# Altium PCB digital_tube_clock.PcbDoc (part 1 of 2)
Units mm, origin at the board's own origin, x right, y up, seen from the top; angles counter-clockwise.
Board outline 78.99 x 94.23 mm, 2 copper layers (Top Layer, Bottom Layer); 32 components, 49 nets, 189 pads, 6 vias.
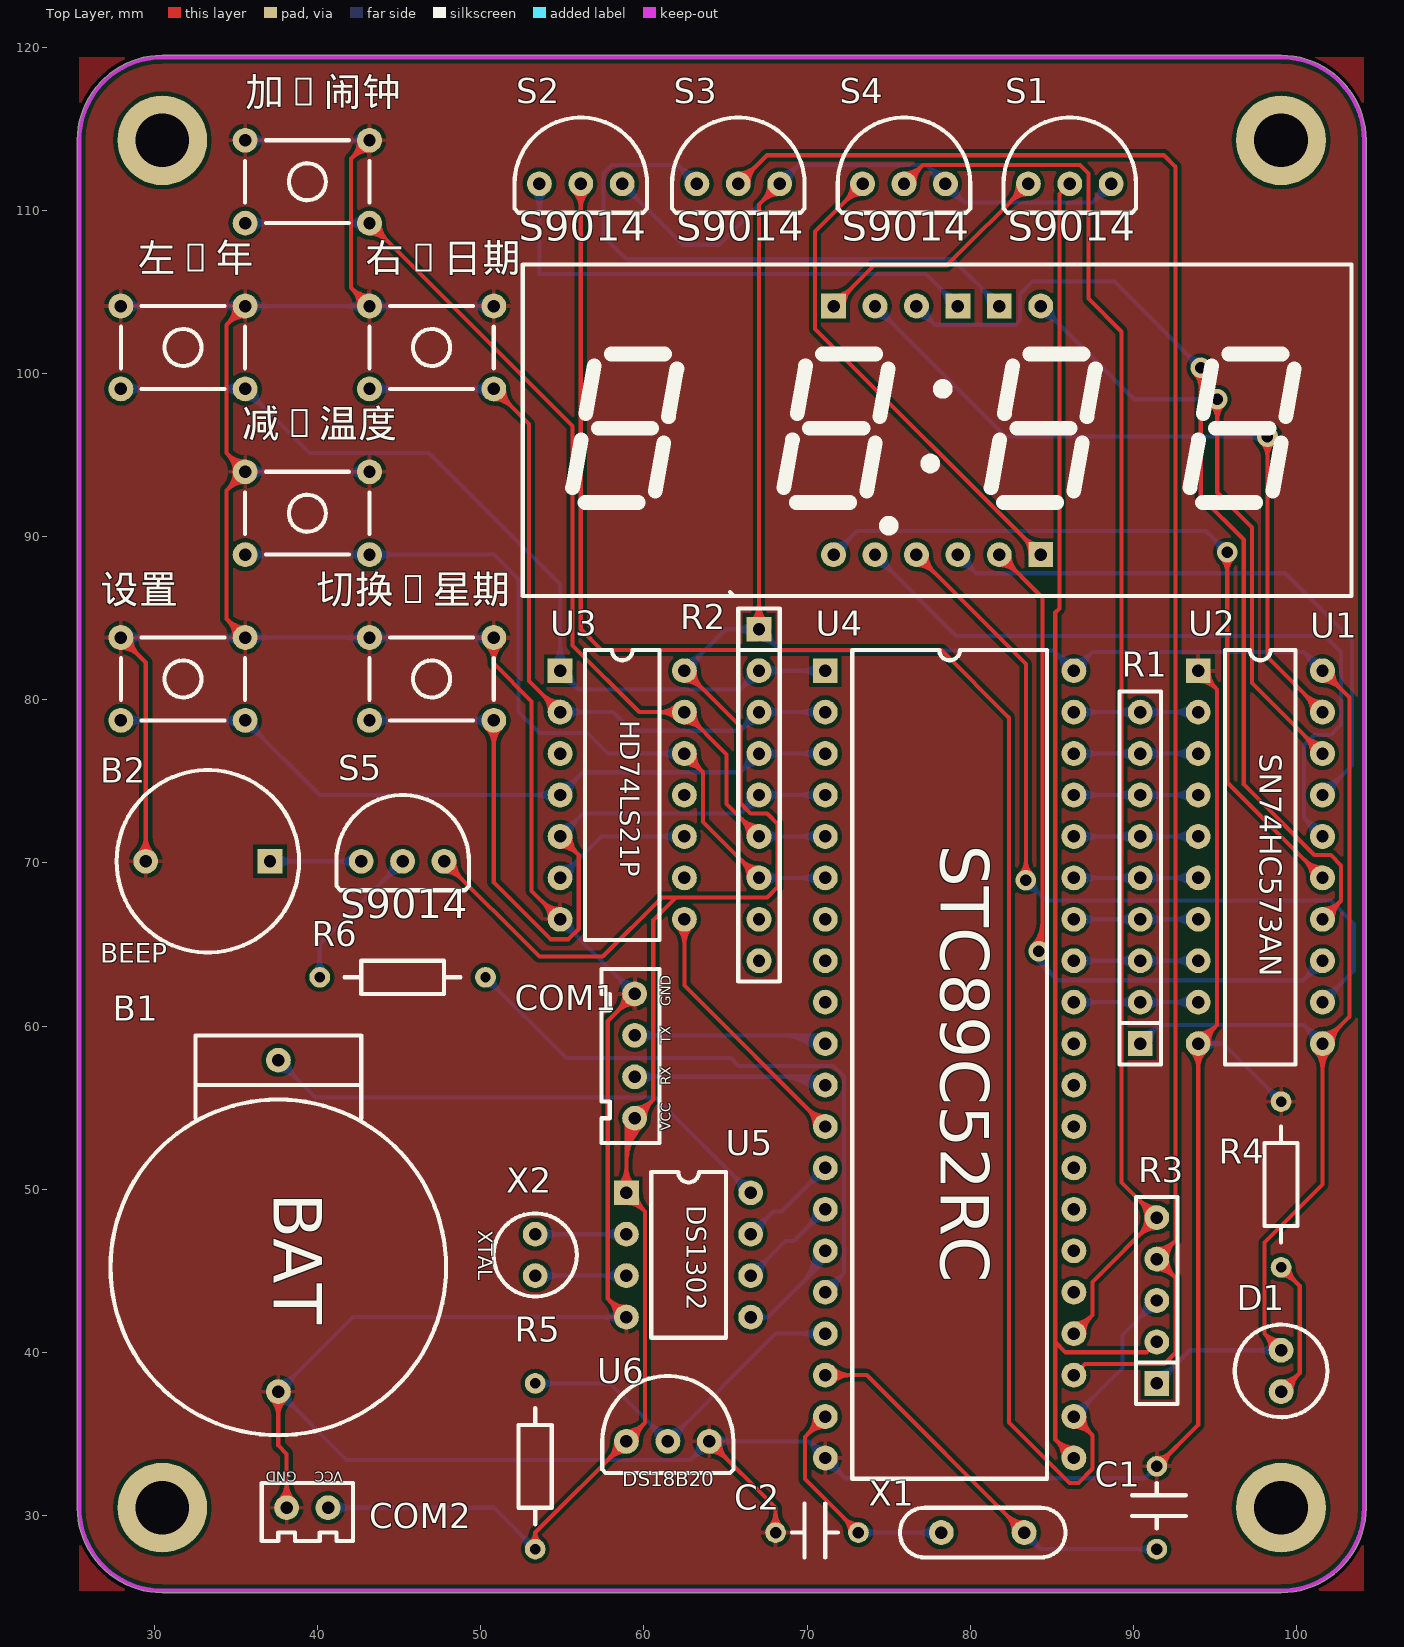
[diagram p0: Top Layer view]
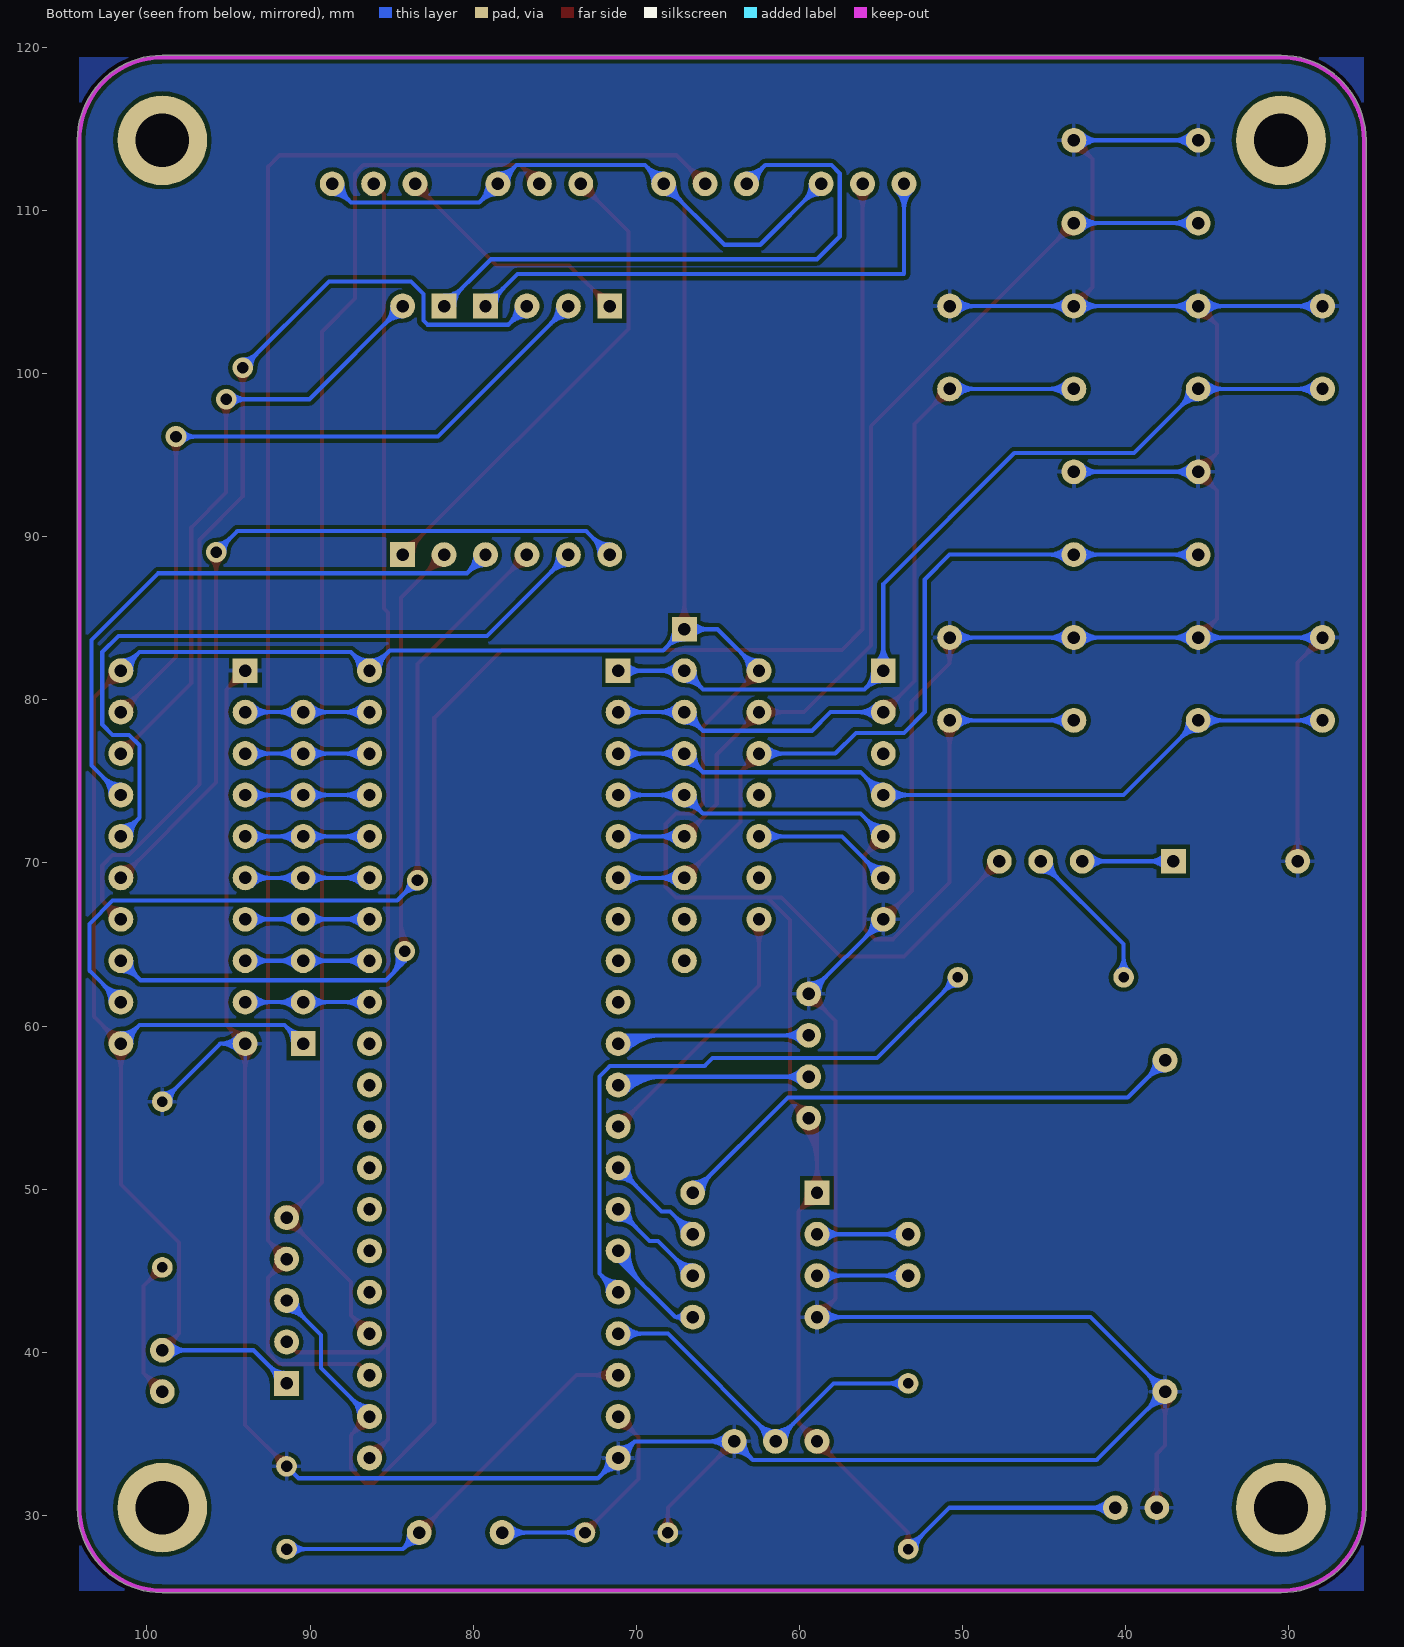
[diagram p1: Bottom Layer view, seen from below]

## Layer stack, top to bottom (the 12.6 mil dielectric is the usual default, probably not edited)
Top Layer: signal copper 0.0356
Dielectric: dielectric 0.32, FR-4, Dk 4.8
Bottom Layer: signal copper 0.0356

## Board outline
25.273,30.479 cw(c30.48,30.48) 25.273,30.48 25.273,114.3 cw(c30.48,114.3) 30.48,119.507 99.06,119.507 cw(c99.06,114.3) 104.267,114.301 cw(c104.14,114.3) 104.267,114.3 104.267,30.48 cw(c99.06,30.48) 99.061,25.273 cw(c99.06,25.4) 99.06,25.273 30.48,25.273 cw(c30.48,30.48)

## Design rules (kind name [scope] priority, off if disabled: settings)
Clearance [All] p1: gap=0.254
ComponentClearance [All] p1: gap=0.254 collisioncheckmode=3 verticalgap=0.254
PolygonConnect [All] p1: connectstyle=Relief reliefconductorwidth=0.254 reliefentries=4 polygonreliefangle="90 Angle"
RoutingVias [All] p1: holewidth=0.711 width=1.27 viastyle="Through Hole" minholewidth=0.711 minwidth=1.27 maxholewidth=0.711 maxwidth=1.27
SolderMaskExpansion [All] p1: expansion=0.102
TestPointUsage [All] p1: valid=0 allowmultiple=FALSE
Testpoint [All] p1: side=15 testpointundercomponent=TRUE minsize=1.016 maxsize=2.54 preferedsize=1.524 minholesize=0 maxholesize=1.016 preferedholesize=0.813 testpointgrid=0.025 style=1023 order=0123456789
Width [All] p1: maxlimit=0.254 minlimit=0.254 preferedwidth=0.254
18 further rules are at their usual default settings.

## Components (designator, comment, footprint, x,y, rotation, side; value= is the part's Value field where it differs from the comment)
B1 "BATTERY" BAT 35.052,57.912 r0 top
B2 "BEEP" BEEP 37.084,70.104 r180 top
C1 "CAP" CAP 91.44,35.56 r270 top
C2 "CAP" CAP 65.532,28.956 r0 top
COM1 "COM" COM4 59.436,54.356 r90 top
COM2 "COM" COM2 43.18,30.48 r180 top
D1 "LED" LED 99.06,40.132 r270 top
R1 "RES8" RES8 90.424,58.928 r180 top
R2 "RES8" RES8 67.056,84.328 r0 top
R3 "RES4" RES4 91.44,38.1 r180 top
R4 "RES" RES 99.06,45.212 r90 top
R5 "RES" RES 53.34,38.1 r270 top
R6 "RES" RES 50.292,62.992 r180 top
S1 "S9014" S9014 83.566,111.633 r0 top
S2 "S9014" S9014 53.594,111.633 r0 top
S3 "S9014" S9014 63.246,111.633 r0 top
S4 "S9014" S9014 73.406,111.633 r0 top
S5 "S9014" S9014 42.672,70.104 r0 top
U1 "DIGITAL_TUBE" DIGITAL 51.308,106.68 r0 top
U2 "SN74HC573AN" SN74HC573AN 93.98,81.788 r0 top
U3 "HD74LS21P" HD74LS21P 54.864,81.788 r0 top
U4 "STC89C52RC" STC89C52RC 71.12,81.788 r0 top
U5 "DS1302" DS1302 58.928,49.784 r0 top
U6 "DS18B20" DS18B20 58.928,34.544 r0 top
X1 "XTAL" XTAL 78.232,28.956 r0 top
X2 "36" XTAL36 53.34,47.244 r270 top
减/温度 "BUTTON" BUTTON 35.56,93.98 r0 top (schematic designator K6)
切换/星期 "BUTTON" BUTTON 43.18,83.82 r0 top (schematic designator K4)
加/闹钟 "BUTTON" BUTTON 35.56,114.3 r0 top (schematic designator K5)
右/日期 "BUTTON" BUTTON 43.18,104.14 r0 top (schematic designator K2)
左/年 "BUTTON" BUTTON 27.94,104.14 r0 top (schematic designator K1)
设置 "BUTTON" BUTTON 27.94,83.82 r0 top (schematic designator K3)

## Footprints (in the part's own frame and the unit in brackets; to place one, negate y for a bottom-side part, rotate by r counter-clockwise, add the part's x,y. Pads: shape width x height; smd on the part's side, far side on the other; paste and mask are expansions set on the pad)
BAT [mil]
  round 60 hole 30: GND(100,-800) VCC(100,0)
  silkscreen extent -305,-905 505,60
BEEP [mil]
  rect 60x60 hole 30: 1(0,0)
  round 60 hole 30: 2(300,0)
  silkscreen extent -70,-220 370,220
BUTTON [mil]
  round 60 hole 30: 1(0,0) 1(300,0) 2(0,-200) 2(300,-200)
  silkscreen extent 0,-200 300,0
CAP [mil]
  round 50 hole 28: 1(100,0) 2(300,0)
  silkscreen extent 140,-60 250,70
COM2 [mil]
  round 60 hole 30: GND(200,0) VCC(100,0)
  silkscreen extent 40,-60 260,80
COM4 [mil]
  round 60 hole 30: GND(300,0) RX(100,0) TX(200,0) VCC(0,0)
  silkscreen extent -60,-60 360,80
DIGITAL [mil] "LED, 7-Segment Display, 10 mm, Three Digit; 15 Leads (4 Absent); Row Space 10.16 mm; Pitch 2.54 mm"
  rect 60x60 hole 30: 1(800,-100) 2(1100,-100) 3(1200,-100) 4(1300,-700)
  round 60 hole 30: a(900,-100) b(1300,-100) c(1100,-700) d(900,-700) e(800,-700) f(1000,-100) g(1200,-700) h(1000,-700)
  silkscreen extent 50,-800 2050,0
DS18B20 [mil]
  round 60 hole 30: DQ(100,0) GND(200,0) VDD(0,0)
  silkscreen extent -58,-76 258,158
DS1302 [mil]
  rect 60x60 hole 30: 1(0,0)
  round 60 hole 30: 2(0,-100) 3(0,-200) 4(0,-300) 5(300,-300) 6(300,-200) 7(300,-100) 8(300,0)
  silkscreen extent 60,-350 240,50
HD74LS21P [mil]
  rect 60x60 hole 30: 1(0,0)
  round 60 hole 30: 2(0,-100) 3(0,-200) 4(0,-300) 5(0,-400) 6(0,-500) 7(0,-600) 8(300,-600) 9(300,-500) 10(300,-400) 11(300,-300) 12(300,-200) 13(300,-100) 14(300,0)
  silkscreen extent 60,-650 240,50
LED [mil]
  round 60 hole 30: 1(0,0) 2(100,0)
  silkscreen extent -62,-112 162,112
RES [mm]
  round 1.27 hole 0.635: 1(0,0) 2(10.16,0)
  silkscreen extent 1.52,-1.02 8.64,1.02
RES4 [mil]
  rect 60x60 hole 30: 1(0,0)
  round 60 hole 30: 2(0,-100) 3(0,-200) 4(0,-300) 5(0,-400)
  silkscreen extent -50,-450 50,50
RES8 [mil]
  rect 60x60 hole 30: 1(0,0)
  round 60 hole 30: 2(0,-100) 3(0,-200) 4(0,-300) 5(0,-400) 6(0,-500) 7(0,-600) 8(0,-700) 9(0,-800)
  silkscreen extent -50,-850 50,50
S9014 [mil]
  round 60 hole 30: b(100,0) c(200,0) e(0,0)
  silkscreen extent -60,-70 260,160
SN74HC573AN [mil]
  rect 60x60 hole 30: 1(0,0)
  round 60 hole 30: 2(0,-100) 3(0,-200) 4(0,-300) 5(0,-400) 6(0,-500) 7(0,-600) 8(0,-700) 9(0,-800) 10(0,-900) 11(300,-900) 12(300,-800) 13(300,-700) 14(300,-600) 15(300,-500) 16(300,-400) 17(300,-300) 18(300,-200) 19(300,-100) 20(300,0)
  silkscreen extent 65,-950 235,50
STC89C52RC [mil]
  rect 60x60 / inner rect 60x6 / far side rect 60x60 hole 30: 1(0,0)
  round 60 / inner oval 60x6 / far side round 60 hole 30: 2(0,-100) 3(0,-200) 4(0,-300) 5(0,-400) 6(0,-500) 7(0,-600) 8(0,-700) 9(0,-800) 10(0,-900) 11(0,-1000) 12(0,-1100) 13(0,-1200) 14(0,-1300) 15(0,-1400) 16(0,-1500) 17(0,-1600) 18(0,-1700) 19(0,-1800) 20(0,-1900) 21(600,-1900) 22(600,-1800) 23(600,-1700) 24(600,-1600) 25(600,-1500) 26(600,-1400) 27(600,-1300) 28(600,-1200) 29(600,-1100) 30(600,-1000) 31(600,-900) 32(600,-800) 33(600,-700) 34(600,-600) 35(600,-500) 36(600,-400) 37(600,-300) 38(600,-200) 39(600,-100) 40(600,0)
  silkscreen extent 65,-1950 535,50
XTAL [mil]
  round 60 hole 30: 1(0,0) 2(200,0)
  silkscreen extent -100,-60 300,60
XTAL36 [mil]
  round 60 hole 30: 1(100,0) 2(0,0)
  silkscreen extent -50,-100 150,100

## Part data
C1 C2: "Capacitance"
COM1: library part COM4, "Download interface"
COM2: library part COM2, "Power interface"
D1: "The power led"
R1 R2: "Resistance * 8"
R3: "Resistance * 4"
R4 R5 R6: "Resistance"
U1: "Dispaly panel"
U4: "8-Bit Microcontroller with 8K ISP Flash ROM"
U5: "Trickle Charge Timekeeping Chip"
U6: library part D18B20, "Programmable Resolution  1-Wire Digital Thermometer"
X1: "Generate system clock"
X2: library part XTAL36

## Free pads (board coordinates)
  round 5.5 hole 3.3: 0(30.48,114.3) 1(99.06,114.3) 2(30.48,30.48) 3(99.06,30.48)

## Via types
v1: diameter 1.27, hole 0.711, Top Layer to Bottom Layer, 6 vias

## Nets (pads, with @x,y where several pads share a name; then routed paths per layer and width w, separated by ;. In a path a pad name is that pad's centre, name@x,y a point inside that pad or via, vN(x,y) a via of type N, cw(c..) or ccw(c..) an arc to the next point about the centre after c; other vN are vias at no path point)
BEEP: R6.1 U4.16 | length 44
  Bottom Layer w0.254: R6.1@50.292,62.484 cw(c50.292,61.258) 51.159,62.125 cw(c52.026,62.992) R6.1@50.8,62.992 ; R6.1@50.292,62.992 55.245,58.039 65.329,58.039 65.811,57.556 71.628,57.556 72.263,56.921 72.263,44.831 U4.16@71.12,43.688 ; U4.16@71.12,44.069 ccw(c71.12,44.989) 71.77,44.338 ccw(c72.421,43.688) U4.16@71.501,43.688 ; U4.16@71.12,44.323 ccw(c71.12,45.856) 72.204,44.772 ccw(c73.288,43.688) U4.16@71.755,43.688
DATA: U4.14 U5.6 | length 14
  Bottom Layer w0.254: U5.6@66.548,44.704 68.679,46.835 69.187,46.835 U4.14@71.12,48.768 ; U5.6@66.548,45.085 ccw(c66.548,46.005) 67.198,45.354 ccw(c67.849,44.704) U5.6@66.929,44.704 ; U5.6@66.548,45.339 ccw(c66.548,46.872) 67.632,45.788 ccw(c68.716,44.704) U5.6@67.183,44.704 ; U4.14@70.485,48.768 cw(c68.952,48.768) 70.036,47.684 cw(c71.12,46.6) U4.14@71.12,48.133 ; U4.14@70.739,48.768 cw(c69.819,48.768) 70.47,48.118 cw(c71.12,47.467) U4.14@71.12,48.387
DIG1: R3.2 S1.b U4.21 | length 89.5
  Top Layer w0.254: U4.21@85.725,33.528 ccw(c84.192,33.528) 85.276,34.612 ccw(c86.36,35.696) U4.21@86.36,34.163 ; U4.21@85.979,33.528 ccw(c85.059,33.528) 85.71,34.178 ccw(c86.36,34.829) U4.21@86.36,33.909 ; S1.b@86.106,111.633 85.471,110.998 85.471,85.598 85.217,85.344 85.217,40.64 ; U4.21@86.36,33.528 85.217,34.671 85.217,40.64 ; R3.2@91.44,40.64 90.805,40.005 85.852,40.005 85.217,40.64
DIG2: R3.3 S2.b U4.22 | length 134.3
  Top Layer w0.254: S2.b@55.685,111.184 cw(c54.601,110.1) 56.134,110.1 cw(c57.667,110.1) S2.b@56.583,111.184 ; S2.b@55.865,111.364 cw(c55.214,110.713) 56.134,110.713 cw(c57.054,110.713) S2.b@56.403,111.364 ; S2.b@56.134,111.633 56.134,84.328 57.404,83.058 78.232,83.058 82.39,78.9 82.39,35.694 86.081,32.004 86.639,32.004 87.503,32.868 87.503,34.925 U4.22@86.36,36.068 ; U4.22@86.36,35.433 cw(c86.36,33.9) 87.444,34.984 cw(c88.528,36.068) U4.22@86.995,36.068 ; U4.22@86.36,35.687 cw(c86.36,34.767) 87.01,35.418 cw(c87.661,36.068) U4.22@86.741,36.068
  Bottom Layer w0.254: U4.22@86.36,36.068 89.332,39.04 89.332,41.072 R3.3@91.44,43.18 ; U4.22@86.36,36.449 ccw(c86.36,37.369) 87.01,36.718 ccw(c87.661,36.068) U4.22@86.741,36.068 ; U4.22@86.36,36.703 ccw(c86.36,38.236) 87.444,37.152 ccw(c88.528,36.068) U4.22@86.995,36.068 ; R3.3@90.805,43.18 cw(c89.272,43.18) 90.356,42.096 cw(c91.44,41.012) R3.3@91.44,42.545 ; R3.3@91.059,43.18 cw(c90.139,43.18) 90.79,42.53 cw(c91.44,41.879) R3.3@91.44,42.799
DIG3: R3.4 S3.b U4.23 | length 119.8
  Top Layer w0.254: S3.b@65.786,111.633 67.539,113.386 91.872,113.386 92.583,112.674 92.583,46.863 R3.4@91.44,45.72 92.583,44.577 92.583,39.98 91.897,39.294 87.046,39.294 U4.23@86.36,38.608 ; S3.b@65.786,112.014 ccw(c65.786,112.934) 66.436,112.283 ccw(c67.087,111.633) S3.b@66.167,111.633 ; S3.b@65.786,112.268 ccw(c65.786,113.801) 66.87,112.717 ccw(c67.954,111.633) S3.b@66.421,111.633 ; R3.4@91.44,45.085 cw(c91.44,43.552) 92.524,44.636 cw(c93.608,45.72) 92.075,45.72 cw(c93.608,45.72) 92.524,46.804 cw(c91.44,47.888) R3.4@91.44,46.355 ; R3.4@91.44,45.339 cw(c91.44,44.419) 92.09,45.07 cw(c92.741,45.72) 91.821,45.72 cw(c92.741,45.72) 92.09,46.37 cw(c91.44,47.021) R3.4@91.44,46.101
DIG4: R3.5 S4.b U4.24 | length 102.4
  Top Layer w0.254: S4.b@75.946,111.633 77.089,112.776 86.741,112.776 87.249,112.268 87.249,104.597 89.281,102.565 89.281,50.419 R3.5@91.44,48.26 87.503,44.323 87.503,42.291 U4.24@86.36,41.148 ; S4.b@75.946,112.014 ccw(c75.946,112.934) 76.596,112.283 ccw(c77.247,111.633) S4.b@76.327,111.633 ; S4.b@75.946,112.268 ccw(c75.946,113.801) 77.03,112.717 ccw(c78.114,111.633) S4.b@76.581,111.633 ; U4.24@86.36,41.529 ccw(c86.36,42.449) 87.01,41.798 ccw(c87.661,41.148) U4.24@86.741,41.148 ; U4.24@86.36,41.783 ccw(c86.36,43.316) 87.444,42.232 ccw(c88.528,41.148) U4.24@86.995,41.148 ; R3.5@91.44,47.625 ccw(c91.44,46.092) 90.356,47.176 ccw(c89.272,48.26) 90.805,48.26 ccw(c89.272,48.26) 90.356,49.344 ccw(c91.44,50.428) R3.5@91.44,48.895 ; R3.5@91.44,47.879 ccw(c91.44,46.959) 90.79,47.61 ccw(c90.139,48.26) 91.059,48.26 ccw(c90.139,48.26) 90.79,48.91 ccw(c91.44,49.561) R3.5@91.44,48.641
DQ: R5.1 U4.17 U6.DQ | length 35.5
  Bottom Layer w0.254: R5.1@53.34,38.1 57.912,38.1 U6.DQ@61.468,34.544 68.072,41.148 U4.17@71.12,41.148 ; R5.1@53.699,37.741 cw(c54.566,36.874) 54.566,38.1 cw(c54.566,39.326) R5.1@53.699,38.459 ; U6.DQ@60.833,34.544 ccw(c59.3,34.544) 60.384,35.628 ccw(c61.468,36.712) 61.468,35.179 ccw(c61.468,36.712) 62.552,35.628 ccw(c63.636,34.544) U6.DQ@62.103,34.544 ; U6.DQ@61.087,34.544 ccw(c60.167,34.544) 60.818,35.194 ccw(c61.468,35.845) 61.468,34.925 ccw(c61.468,35.845) 62.118,35.194 ccw(c62.769,34.544) U6.DQ@61.849,34.544 ; U4.17@70.671,40.699 ccw(c69.587,39.615) 69.587,41.148 ccw(c69.587,42.681) U4.17@70.671,41.597 ; U4.17@70.851,40.879 ccw(c70.2,40.228) 70.2,41.148 ccw(c70.2,42.068) U4.17@70.851,41.417
GND: B1.GND B2.2 C1.1 C2.1 COM1.GND COM2.GND R4.2 U2.1 U2.10 U3.7 U4.20 U5.4 U6.GND 减/温度.1 切换/星期.1 加/闹钟.1 右/日期.1 左/年.1 设置.1 | length 482.4
  Top Layer w0.254: 设置.1@27.94,83.185 cw(c27.94,81.652) 29.024,82.736 cw(c30.108,83.82) 设置.1@28.575,83.82 ; 设置.1@27.94,83.439 cw(c27.94,82.519) 28.59,83.17 cw(c29.241,83.82) 设置.1@28.321,83.82 ; 设置.1@27.94,83.82 29.464,82.296 B2.2@29.464,70.104 ; B2.2@29.015,70.553 ccw(c27.931,71.637) 29.464,71.637 ccw(c30.997,71.637) B2.2@29.913,70.553 ; B2.2@29.195,70.373 ccw(c28.544,71.024) 29.464,71.024 ccw(c30.384,71.024) B2.2@29.733,70.373 ; 设置.1@34.925,83.82 ccw(c33.392,83.82) 34.476,84.904 ccw(c35.56,85.988) 设置.1@35.56,84.455 ; 左/年.1@34.925,104.14 cw(c33.392,104.14) 34.476,103.056 cw(c35.56,101.972) 左/年.1@35.56,103.505 ; 设置.1@35.179,83.82 ccw(c34.259,83.82) 34.91,84.47 ccw(c35.56,85.121) 设置.1@35.56,84.201 ; 左/年.1@35.179,104.14 cw(c34.259,104.14) 34.91,103.49 cw(c35.56,102.839) 左/年.1@35.56,103.759 ; 设置.1@35.56,83.82 34.417,84.963 34.417,92.837 减/温度.1@35.56,93.98 34.417,95.123 34.417,102.997 左/年.1@35.56,104.14 ; 减/温度.1@35.56,93.345 ccw(c35.56,91.812) 34.476,92.896 ccw(c33.392,93.98) 34.925,93.98 ccw(c33.392,93.98) 34.476,95.064 ccw(c35.56,96.148) 减/温度.1@35.56,94.615 ; 减/温度.1@35.56,93.599 ccw(c35.56,92.679) 34.91,93.33 ccw(c34.259,93.98) 35.179,93.98 ccw(c34.259,93.98) 34.91,94.63 ccw(c35.56,95.281) 减/温度.1@35.56,94.361 ; B1.GND@37.143,37.143 cw(c36.059,36.059) 37.592,36.059 cw(c39.125,36.059) B1.GND@38.041,37.143 ; B1.GND@37.323,37.323 cw(c36.672,36.672) 37.592,36.672 cw(c38.512,36.672) B1.GND@37.861,37.323 ; B1.GND@37.592,37.592 37.592,34.29 38.1,33.782 COM2.GND@38.1,30.48 ; COM2.GND@37.651,30.929 ccw(c36.567,32.013) 38.1,32.013 ccw(c39.633,32.013) COM2.GND@38.549,30.929 ; COM2.GND@37.831,30.749 ccw(c37.18,31.4) 38.1,31.4 ccw(c39.02,31.4) COM2.GND@38.369,30.749 ; 右/日期.1@42.545,104.14 ccw(c41.012,104.14) 42.096,105.224 ccw(c43.18,106.308) 右/日期.1@43.18,104.775 ; 加/闹钟.1@42.545,114.3 cw(c41.012,114.3) 42.096,113.216 cw(c43.18,112.132) 加/闹钟.1@43.18,113.665 ; 右/日期.1@42.799,104.14 ccw(c41.879,104.14) 42.53,104.79 ccw(c43.18,105.441) 右/日期.1@43.18,104.521 ; 加/闹钟.1@42.799,114.3 cw(c41.879,114.3) 42.53,113.65 cw(c43.18,112.999) 加/闹钟.1@43.18,113.919 ; 右/日期.1@43.18,104.14 42.037,105.283 42.037,113.157 加/闹钟.1@43.18,114.3 ; 切换/星期.1@50.351,83.371 cw(c49.267,82.287) 50.8,82.287 cw(c52.333,82.287) 切换/星期.1@51.249,83.371 ; 切换/星期.1@50.531,83.551 cw(c49.88,82.9) 50.8,82.9 cw(c51.72,82.9) 切换/星期.1@51.069,83.551 ; 切换/星期.1@50.8,83.82 50.8,82.22 53.119,79.901 53.119,68.293 U3.7@54.864,66.548 ; U3.7@54.229,66.548 ccw(c52.696,66.548) 53.78,67.632 ccw(c54.864,68.716) U3.7@54.864,67.183 ; U3.7@54.483,66.548 ccw(c53.563,66.548) 54.214,67.198 ccw(c54.864,67.849) U3.7@54.864,66.929 ; U5.4@58.293,42.164 ccw(c56.76,42.164) 57.844,43.248 ccw(c58.928,44.332) U5.4@58.928,42.799 ; U5.4@58.547,42.164 ccw(c57.627,42.164) 58.278,42.814 ccw(c58.928,43.465) U5.4@58.928,42.545 ; COM1.GND@58.801,61.976 cw(c57.268,61.976) 58.352,60.892 cw(c59.436,59.808) COM1.GND@59.436,61.341 ; U5.4@58.928,42.164 57.785,43.307 57.785,60.325 COM1.GND@59.436,61.976 ; COM1.GND@59.055,61.976 cw(c58.135,61.976) 58.786,61.326 cw(c59.436,60.675) COM1.GND@59.436,61.595 ; U6.GND@64.008,33.909 cw(c64.008,32.376) 65.092,33.46 cw(c66.176,34.544) U6.GND@64.643,34.544 ; U6.GND@64.008,34.163 cw(c64.008,33.243) 64.658,33.894 cw(c65.309,34.544) U6.GND@64.389,34.544 ; U6.GND@64.008,34.544 68.072,30.48 C2.1@68.072,28.956 ; C2.1@67.713,29.315 ccw(c66.846,30.182) 68.072,30.182 ccw(c69.298,30.182) C2.1@68.431,29.315 ; C1.1@91.44,33.02 93.98,35.56 U2.10@93.98,58.928 95.123,60.071 95.123,80.645 U2.1@93.98,81.788 ; C1.1@91.44,33.528 ccw(c91.44,34.754) 92.307,33.887 ccw(c93.174,33.02) C1.1@91.948,33.02 ; U2.10@93.531,58.479 cw(c92.447,57.395) 93.98,57.395 cw(c95.513,57.395) U2.10@94.429,58.479 ; U2.10@93.711,58.659 cw(c93.06,58.008) 93.98,58.008 cw(c94.9,58.008) U2.10@94.249,58.659 ; U2.10@93.98,59.309 ccw(c93.98,60.229) 94.63,59.578 ccw(c95.281,58.928) U2.10@94.361,58.928 ; U2.10@93.98,59.563 ccw(c93.98,61.096) 95.064,60.012 ccw(c96.148,58.928) U2.10@94.615,58.928 ; U2.1@93.98,81.153 cw(c93.98,79.62) 95.064,80.704 cw(c96.148,81.788) U2.1@94.615,81.788 ; U2.1@93.98,81.407 cw(c93.98,80.487) 94.63,81.138 cw(c95.281,81.788) U2.1@94.361,81.788
  Bottom Layer w0.254: 设置.1@27.94,83.82 设置.1@35.56,83.82 切换/星期.1@43.18,83.82 切换/星期.1@50.8,83.82 ; 左/年.1@27.94,104.14 左/年.1@35.56,104.14 右/日期.1@43.18,104.14 右/日期.1@50.8,104.14 ; 设置.1@28.209,83.551 cw(c28.86,82.9) 28.86,83.82 cw(c28.86,84.74) 设置.1@28.209,84.089 ; 左/年.1@28.209,103.871 cw(c28.86,103.22) 28.86,104.14 cw(c28.86,105.06) 左/年.1@28.209,104.409 ; 设置.1@28.389,83.371 cw(c29.473,82.287) 29.473,83.82 cw(c29.473,85.353) 设置.1@28.389,84.269 ; 左/年.1@28.389,103.691 cw(c29.473,102.607) 29.473,104.14 cw(c29.473,105.673) 左/年.1@28.389,104.589 ; 设置.1@35.111,83.371 ccw(c34.027,82.287) 34.027,83.82 ccw(c34.027,85.353) 设置.1@35.111,84.269 ; 左/年.1@35.111,103.691 ccw(c34.027,102.607) 34.027,104.14 ccw(c34.027,105.673) 左/年.1@35.111,104.589 ; 设置.1@35.291,83.551 ccw(c34.64,82.9) 34.64,83.82 ccw(c34.64,84.74) 设置.1@35.291,84.089 ; 左/年.1@35.291,103.871 ccw(c34.64,103.22) 34.64,104.14 ccw(c34.64,105.06) 左/年.1@35.291,104.409 ; 减/温度.1@35.56,93.98 减/温度.1@43.18,93.98 ; 加/闹钟.1@35.56,114.3 加/闹钟.1@43.18,114.3 ; 设置.1@35.829,83.551 cw(c36.48,82.9) 36.48,83.82 cw(c36.48,84.74) 设置.1@35.829,84.089 ; 减/温度.1@35.829,93.711 cw(c36.48,93.06) 36.48,93.98 cw(c36.48,94.9) 减/温度.1@35.829,94.249 ; 左/年.1@35.829,103.871 cw(c36.48,103.22) 36.48,104.14 cw(c36.48,105.06) 左/年.1@35.829,104.409 ; 加/闹钟.1@35.829,114.031 cw(c36.48,113.38) 36.48,114.3 cw(c36.48,115.22) 加/闹钟.1@35.829,114.569 ; 设置.1@36.009,83.371 cw(c37.093,82.287) 37.093,83.82 cw(c37.093,85.353) 设置.1@36.009,84.269 ; 减/温度.1@36.009,93.531 cw(c37.093,92.447) 37.093,93.98 cw(c37.093,95.513) 减/温度.1@36.009,94.429 ; 左/年.1@36.009,103.691 cw(c37.093,102.607) 37.093,104.14 cw(c37.093,105.673) 左/年.1@36.009,104.589 ; 加/闹钟.1@36.009,113.851 cw(c37.093,112.767) 37.093,114.3 cw(c37.093,115.833) 加/闹钟.1@36.009,114.749 ; B1.GND@37.592,36.957 cw(c37.592,35.424) 38.676,36.508 cw(c39.76,37.592) 38.227,37.592 cw(c39.76,37.592) 38.676,38.676 cw(c37.592,39.76) B1.GND@37.592,38.227 ; B1.GND@37.592,37.211 cw(c37.592,36.291) 38.242,36.942 cw(c38.893,37.592) 37.973,37.592 cw(c38.893,37.592) 38.242,38.242 cw(c37.592,38.893) B1.GND@37.592,37.973 ; 切换/星期.1@42.731,83.371 ccw(c41.647,82.287) 41.647,83.82 ccw(c41.647,85.353) 切换/星期.1@42.731,84.269 ; 减/温度.1@42.731,93.531 ccw(c41.647,92.447) 41.647,93.98 ccw(c41.647,95.513) 减/温度.1@42.731,94.429 ; 右/日期.1@42.731,103.691 ccw(c41.647,102.607) 41.647,104.14 ccw(c41.647,105.673) 右/日期.1@42.731,104.589 ; 加/闹钟.1@42.731,113.851 ccw(c41.647,112.767) 41.647,114.3 ccw(c41.647,115.833) 加/闹钟.1@42.731,114.749 ; 切换/星期.1@42.911,83.551 ccw(c42.26,82.9) 42.26,83.82 ccw(c42.26,84.74) 切换/星期.1@42.911,84.089 ; 减/温度.1@42.911,93.711 ccw(c42.26,93.06) 42.26,93.98 ccw(c42.26,94.9) 减/温度.1@42.911,94.249 ; 右/日期.1@42.911,103.871 ccw(c42.26,103.22) 42.26,104.14 ccw(c42.26,105.06) 右/日期.1@42.911,104.409 ; 加/闹钟.1@42.911,114.031 ccw(c42.26,113.38) 42.26,114.3 ccw(c42.26,115.22) 加/闹钟.1@42.911,114.569 ; 切换/星期.1@43.449,83.551 cw(c44.1,82.9) 44.1,83.82 cw(c44.1,84.74) 切换/星期.1@43.449,84.089 ; 右/日期.1@43.449,103.871 cw(c44.1,103.22) 44.1,104.14 cw(c44.1,105.06) 右/日期.1@43.449,104.409 ; 切换/星期.1@43.629,83.371 cw(c44.713,82.287) 44.713,83.82 cw(c44.713,85.353) 切换/星期.1@43.629,84.269 ; 右/日期.1@43.629,103.691 cw(c44.713,102.607) 44.713,104.14 cw(c44.713,105.673) 右/日期.1@43.629,104.589 ; 切换/星期.1@50.351,83.371 ccw(c49.267,82.287) 49.267,83.82 ccw(c49.267,85.353) 切换/星期.1@50.351,84.269 ; 右/日期.1@50.351,103.691 ccw(c49.267,102.607) 49.267,104.14 ccw(c49.267,105.673) 右/日期.1@50.351,104.589 ; 切换/星期.1@50.531,83.551 ccw(c49.88,82.9) 49.88,83.82 ccw(c49.88,84.74) 切换/星期.1@50.531,84.089 ; 右/日期.1@50.531,103.871 ccw(c49.88,103.22) 49.88,104.14 ccw(c49.88,105.06) 右/日期.1@50.531,104.409 ; U3.7@54.864,65.913 cw(c54.864,64.38) 55.948,65.464 cw(c57.032,66.548) U3.7@55.499,66.548 ; U3.7@54.864,66.167 cw(c54.864,65.247) 55.514,65.898 cw(c56.165,66.548) U3.7@55.245,66.548 ; U3.7@54.864,66.548 COM1.GND@59.436,61.976 ; U5.4@58.479,41.715 ccw(c57.395,40.631) 57.395,42.164 ccw(c57.395,43.697) U5.4@58.479,42.613 ; U5.4@58.659,41.895 ccw(c58.008,41.244) 58.008,42.164 ccw(c58.008,43.084) U5.4@58.659,42.433 ; COM1.GND@58.801,61.976 ccw(c57.268,61.976) 58.352,63.06 ccw(c59.436,64.144) COM1.GND@59.436,62.611 ; U5.4@58.928,42.164 42.164,42.164 B1.GND@37.592,37.592 41.783,33.401 62.865,33.401 U6.GND@64.008,34.544 70.104,34.544 ; COM1.GND@59.055,61.976 ccw(c58.135,61.976) 58.786,62.626 ccw(c59.436,63.277) COM1.GND@59.436,62.357 ; U6.GND@63.373,34.544 cw(c61.84,34.544) 62.924,33.46 cw(c64.008,32.376) U6.GND@64.008,33.909 ; U6.GND@63.627,34.544 cw(c62.707,34.544) 63.358,33.894 cw(c64.008,33.243) U6.GND@64.008,34.163 ; U6.GND@64.277,34.275 cw(c64.928,33.624) 64.928,34.544 cw(c64.928,35.464) U6.GND@64.277,34.813 ; U6.GND@64.457,34.095 cw(c65.541,33.011) 65.541,34.544 cw(c65.541,36.077) U6.GND@64.457,34.993 ; U4.20@70.486,33.558 ccw(c69.179,33.619) 70.104,34.544 ; U4.20@70.739,33.546 ccw(c69.956,33.583) 70.51,34.138 ccw(c71.065,34.692) U4.20@71.102,33.909 ; U4.20@71.09,34.162 cw(c71.029,35.469) 70.104,34.544 ; U4.20@71.12,32.893 cw(c71.12,31.36) 72.204,32.444 cw(c73.288,33.528) U4.20@71.755,33.528 ; U4.20@71.12,33.147 cw(c71.12,32.227) 71.77,32.878 cw(c72.421,33.528) U4.20@71.501,33.528 ; C1.1@91.44,33.02 90.703,32.283 72.365,32.283 U4.20@71.12,33.528 70.104,34.544 ; U2.10@93.98,58.928 95.504,58.928 ; U2.10@94.251,58.66 cw(c94.894,58.021) 94.894,58.928 cw(c94.894,59.835) U2.10@94.251,59.196 ; U2.10@94.431,58.481 cw(c95.504,57.417) 95.504,58.928 ; U2.10@94.431,59.375 ccw(c95.504,60.439) 95.504,58.928 ; R4.2@98.552,55.372 ccw(c97.326,55.372) 98.193,56.239 ccw(c99.06,57.106) R4.2@99.06,55.88 ; R4.2@99.06,55.372 95.504,58.928
INT0: U3.8 U4.12 | length 24
  Top Layer w0.254: U3.8@62.035,66.099 cw(c60.951,65.015) 62.484,65.015 cw(c64.017,65.015) U3.8@62.933,66.099 ; U3.8@62.215,66.279 cw(c61.564,65.628) 62.484,65.628 cw(c63.404,65.628) U3.8@62.753,66.279 ; U3.8@62.484,66.548 62.484,62.484 U4.12@71.12,53.848 ; U4.12@70.485,53.848 ccw(c68.952,53.848) 70.036,54.932 ccw(c71.12,56.016) U4.12@71.12,54.483 ; U4.12@70.739,53.848 ccw(c69.819,53.848) 70.47,54.498 ccw(c71.12,55.149) U4.12@71.12,54.229
K1: R2.2 U3.1 U4.1 左/年.2 | length 85.2
  Bottom Layer w0.254: 左/年.2@27.94,99.06 左/年.2@35.56,99.06 39.497,95.123 46.838,95.123 54.864,87.097 U3.1@54.864,81.788 56.007,80.645 65.913,80.645 R2.2@67.056,81.788 U4.1@71.12,81.788 ; 左/年.2@28.209,98.791 cw(c28.86,98.14) 28.86,99.06 cw(c28.86,99.98) 左/年.2@28.209,99.329 ; 左/年.2@28.389,98.611 cw(c29.473,97.527) 29.473,99.06 cw(c29.473,100.593) 左/年.2@28.389,99.509 ; 左/年.2@35.111,98.611 ccw(c34.027,97.527) 34.027,99.06 ccw(c34.027,100.593) 左/年.2@35.111,99.509 ; 左/年.2@35.291,98.791 ccw(c34.64,98.14) 34.64,99.06 ccw(c34.64,99.98) 左/年.2@35.291,99.329 ; 左/年.2@35.56,98.425 cw(c35.56,96.892) 36.644,97.976 cw(c37.728,99.06) 左/年.2@36.195,99.06 ; 左/年.2@35.56,98.679 cw(c35.56,97.759) 36.21,98.41 cw(c36.861,99.06) 左/年.2@35.941,99.06 ; U3.1@54.415,82.237 ccw(c53.331,83.321) 54.864,83.321 ccw(c56.397,83.321) U3.1@55.313,82.237 ; U3.1@54.595,82.057 ccw(c53.944,82.708) 54.864,82.708 ccw(c55.784,82.708) U3.1@55.133,82.057 ; U3.1@54.864,81.153 cw(c54.864,79.62) 55.948,80.704 cw(c57.032,81.788) U3.1@55.499,81.788 ; U3.1@54.864,81.407 cw(c54.864,80.487) 55.514,81.138 cw(c56.165,81.788) U3.1@55.245,81.788 ; R2.2@66.421,81.788 cw(c64.888,81.788) 65.972,80.704 cw(c67.056,79.62) R2.2@67.056,81.153 ; R2.2@66.675,81.788 cw(c65.755,81.788) 66.406,81.138 cw(c67.056,80.487) R2.2@67.056,81.407 ; R2.2@67.325,81.519 cw(c67.976,80.868) 67.976,81.788 cw(c67.976,82.708) R2.2@67.325,82.057 ; R2.2@67.505,81.339 cw(c68.589,80.255) 68.589,81.788 cw(c68.589,83.321) R2.2@67.505,82.237 ; U4.1@70.671,81.339 ccw(c69.587,80.255) 69.587,81.788 ccw(c69.587,83.321) U4.1@70.671,82.237 ; U4.1@70.851,81.519 ccw(c70.2,80.868) 70.2,81.788 ccw(c70.2,82.708) U4.1@70.851,82.057
K2: R2.3 U3.2 U4.2 右/日期.2 | length 77.1
  Top Layer w0.254: 右/日期.2@50.8,98.425 cw(c50.8,96.892) 51.884,97.976 cw(c52.968,99.06) 右/日期.2@51.435,99.06 ; 右/日期.2@50.8,98.679 cw(c50.8,97.759) 51.45,98.41 cw(c52.101,99.06) 右/日期.2@51.181,99.06 ; 右/日期.2@50.8,99.06 52.959,96.901 52.959,81.153 U3.2@54.864,79.248 ; U3.2@54.229,79.248 ccw(c52.696,79.248) 53.78,80.332 ccw(c54.864,81.416) U3.2@54.864,79.883 ; U3.2@54.483,79.248 ccw(c53.563,79.248) 54.214,79.898 ccw(c54.864,80.549) U3.2@54.864,79.629
  Bottom Layer w0.254: 右/日期.2@43.18,99.06 右/日期.2@50.8,99.06 ; 右/日期.2@43.449,98.791 cw(c44.1,98.14) 44.1,99.06 cw(c44.1,99.98) 右/日期.2@43.449,99.329 ; 右/日期.2@43.629,98.611 cw(c44.713,97.527) 44.713,99.06 cw(c44.713,100.593) 右/日期.2@43.629,99.509 ; 右/日期.2@50.351,98.611 ccw(c49.267,97.527) 49.267,99.06 ccw(c49.267,100.593) 右/日期.2@50.351,99.509 ; 右/日期.2@50.531,98.791 ccw(c49.88,98.14) 49.88,99.06 ccw(c49.88,99.98) 右/日期.2@50.531,99.329 ; U3.2@54.864,79.248 58.09,79.248 59.233,78.105 65.913,78.105 R2.3@67.056,79.248 U4.2@71.12,79.248 ; U3.2@55.133,78.979 cw(c55.784,78.328) 55.784,79.248 cw(c55.784,80.168) U3.2@55.133,79.517 ; U3.2@55.313,78.799 cw(c56.397,77.715) 56.397,79.248 cw(c56.397,80.781) U3.2@55.313,79.697 ; R2.3@66.421,79.248 cw(c64.888,79.248) 65.972,78.164 cw(c67.056,77.08) R2.3@67.056,78.613 ; R2.3@66.675,79.248 cw(c65.755,79.248) 66.406,78.598 cw(c67.056,77.947) R2.3@67.056,78.867 ; R2.3@67.325,78.979 cw(c67.976,78.328) 67.976,79.248 cw(c67.976,80.168) R2.3@67.325,79.517 ; R2.3@67.505,78.799 cw(c68.589,77.715) 68.589,79.248 cw(c68.589,80.781) R2.3@67.505,79.697 ; U4.2@70.671,78.799 ccw(c69.587,77.715) 69.587,79.248 ccw(c69.587,80.781) U4.2@70.671,79.697 ; U4.2@70.851,78.979 ccw(c70.2,78.328) 70.2,79.248 ccw(c70.2,80.168) U4.2@70.851,79.517
K3: R2.4 U3.4 U4.3 设置.2 | length 76.9
  Bottom Layer w0.254: 设置.2@27.94,78.74 设置.2@35.56,78.74 40.132,74.168 U3.4@54.864,74.168 56.261,75.565 65.913,75.565 R2.4@67.056,76.708 U4.3@71.12,76.708 ; 设置.2@28.209,78.471 cw(c28.86,77.82) 28.86,78.74 cw(c28.86,79.66) 设置.2@28.209,79.009 ; 设置.2@28.389,78.291 cw(c29.473,77.207) 29.473,78.74 cw(c29.473,80.273) 设置.2@28.389,79.189 ; 设置.2@35.111,78.291 ccw(c34.027,77.207) 34.027,78.74 ccw(c34.027,80.273) 设置.2@35.111,79.189 ; 设置.2@35.291,78.471 ccw(c34.64,77.82) 34.64,78.74 ccw(c34.64,79.66) 设置.2@35.291,79.009 ; 设置.2@35.56,78.105 cw(c35.56,76.572) 36.644,77.656 cw(c37.728,78.74) 设置.2@36.195,78.74 ; 设置.2@35.56,78.359 cw(c35.56,77.439) 36.21,78.09 cw(c36.861,78.74) 设置.2@35.941,78.74 ; U3.4@54.415,73.719 ccw(c53.331,72.635) 53.331,74.168 ccw(c53.331,75.701) U3.4@54.415,74.617 ; U3.4@54.595,73.899 ccw(c53.944,73.248) 53.944,74.168 ccw(c53.944,75.088) U3.4@54.595,74.437 ; U3.4@54.864,74.549 ccw(c54.864,75.469) 55.514,74.818 ccw(c56.165,74.168) U3.4@55.245,74.168 ; U3.4@54.864,74.803 ccw(c54.864,76.336) 55.948,75.252 ccw(c57.032,74.168) U3.4@55.499,74.168 ; R2.4@66.421,76.708 cw(c64.888,76.708) 65.972,75.624 cw(c67.056,74.54) R2.4@67.056,76.073 ; R2.4@66.675,76.708 cw(c65.755,76.708) 66.406,76.058 cw(c67.056,75.407) R2.4@67.056,76.327 ; R2.4@67.325,76.439 cw(c67.976,75.788) 67.976,76.708 cw(c67.976,77.628) R2.4@67.325,76.977 ; R2.4@67.505,76.259 cw(c68.589,75.175) 68.589,76.708 cw(c68.589,78.241) R2.4@67.505,77.157 ; U4.3@70.671,76.259 ccw(c69.587,75.175) 69.587,76.708 ccw(c69.587,78.241) U4.3@70.671,77.157 ; U4.3@70.851,76.439 ccw(c70.2,75.788) 70.2,76.708 ccw(c70.2,77.628) U4.3@70.851,76.977
K4: R2.5 U3.5 U4.4 切换/星期.2 | length 78.7
  Top Layer w0.254: 切换/星期.2@50.351,78.291 cw(c49.267,77.207) 50.8,77.207 cw(c52.333,77.207) 切换/星期.2@51.249,78.291 ; 切换/星期.2@50.531,78.471 cw(c49.88,77.82) 50.8,77.82 cw(c51.72,77.82) 切换/星期.2@51.069,78.471 ; 切换/星期.2@50.8,78.74 50.8,68.809 54.28,65.329 55.372,65.329 56.007,65.964 56.007,70.485 U3.5@54.864,71.628 ; U3.5@54.864,70.993 cw(c54.864,69.46) 55.948,70.544 cw(c57.032,71.628) U3.5@55.499,71.628 ; U3.5@54.864,71.247 cw(c54.864,70.327) 55.514,70.978 cw(c56.165,71.628) U3.5@55.245,71.628
  Bottom Layer w0.254: 切换/星期.2@43.18,78.74 切换/星期.2@50.8,78.74 ; 切换/星期.2@43.449,78.471 cw(c44.1,77.82) 44.1,78.74 cw(c44.1,79.66) 切换/星期.2@43.449,79.009 ; 切换/星期.2@43.629,78.291 cw(c44.713,77.207) 44.713,78.74 cw(c44.713,80.273) 切换/星期.2@43.629,79.189 ; 切换/星期.2@50.351,78.291 ccw(c49.267,77.207) 49.267,78.74 ccw(c49.267,80.273) 切换/星期.2@50.351,79.189 ; 切换/星期.2@50.531,78.471 ccw(c49.88,77.82) 49.88,78.74 ccw(c49.88,79.66) 切换/星期.2@50.531,79.009 ; U3.5@54.864,71.628 56.261,73.025 65.913,73.025 R2.5@67.056,74.168 U4.4@71.12,74.168 ; U3.5@54.864,72.009 ccw(c54.864,72.929) 55.514,72.278 ccw(c56.165,71.628) U3.5@55.245,71.628 ; U3.5@54.864,72.263 ccw(c54.864,73.796) 55.948,72.712 ccw(c57.032,71.628) U3.5@55.499,71.628 ; R2.5@66.421,74.168 cw(c64.888,74.168) 65.972,73.084 cw(c67.056,72) R2.5@67.056,73.533 ; R2.5@66.675,74.168 cw(c65.755,74.168) 66.406,73.518 cw(c67.056,72.867) R2.5@67.056,73.787 ; R2.5@67.325,73.899 cw(c67.976,73.248) 67.976,74.168 cw(c67.976,75.088) R2.5@67.325,74.437 ; R2.5@67.505,73.719 cw(c68.589,72.635) 68.589,74.168 cw(c68.589,75.701) R2.5@67.505,74.617 ; U4.4@70.671,73.719 ccw(c69.587,72.635) 69.587,74.168 ccw(c69.587,75.701) U4.4@70.671,74.617 ; U4.4@70.851,73.899 ccw(c70.2,73.248) 70.2,74.168 ccw(c70.2,75.088) U4.4@70.851,74.437
K5: R2.6 U3.13 U4.5 加/闹钟.2 | length 91.6
  Top Layer w0.254: 加/闹钟.2@43.18,108.585 cw(c43.18,107.052) 44.264,108.136 cw(c45.348,109.22) 加/闹钟.2@43.815,109.22 ; 加/闹钟.2@43.18,108.839 cw(c43.18,107.919) 43.83,108.57 cw(c44.481,109.22) 加/闹钟.2@43.561,109.22 ; 加/闹钟.2@43.18,109.22 55.626,96.774 55.626,83.337 59.715,79.248 U3.13@62.484,79.248 65.075,76.657 65.075,73.609 R2.6@67.056,71.628 ; U3.13@62.035,78.799 ccw(c60.951,77.715) 60.951,79.248 ccw(c60.951,80.781) U3.13@62.035,79.697 ; U3.13@62.215,78.979 ccw(c61.564,78.328) 61.564,79.248 ccw(c61.564,80.168) U3.13@62.215,79.517 ; U3.13@62.484,78.613 cw(c62.484,77.08) 63.568,78.164 cw(c64.652,79.248) U3.13@63.119,79.248 ; U3.13@62.484,78.867 cw(c62.484,77.947) 63.134,78.598 cw(c63.785,79.248) U3.13@62.865,79.248 ; R2.6@66.421,71.628 ccw(c64.888,71.628) 65.972,72.712 ccw(c67.056,73.796) R2.6@67.056,72.263 ; R2.6@66.675,71.628 ccw(c65.755,71.628) 66.406,72.278 ccw(c67.056,72.929) R2.6@67.056,72.009
  Bottom Layer w0.254: 加/闹钟.2@35.56,109.22 加/闹钟.2@43.18,109.22 ; 加/闹钟.2@35.829,108.951 cw(c36.48,108.3) 36.48,109.22 cw(c36.48,110.14) 加/闹钟.2@35.829,109.489 ; 加/闹钟.2@36.009,108.771 cw(c37.093,107.687) 37.093,109.22 cw(c37.093,110.753) 加/闹钟.2@36.009,109.669 ; 加/闹钟.2@42.731,108.771 ccw(c41.647,107.687) 41.647,109.22 ccw(c41.647,110.753) 加/闹钟.2@42.731,109.669 ; 加/闹钟.2@42.911,108.951 ccw(c42.26,108.3) 42.26,109.22 ccw(c42.26,110.14) 加/闹钟.2@42.911,109.489 ; R2.6@67.056,71.628 U4.5@71.12,71.628 ; R2.6@67.325,71.359 cw(c67.976,70.708) 67.976,71.628 cw(c67.976,72.548) R2.6@67.325,71.897 ; R2.6@67.505,71.179 cw(c68.589,70.095) 68.589,71.628 cw(c68.589,73.161) R2.6@67.505,72.077 ; U4.5@70.671,71.179 ccw(c69.587,70.095) 69.587,71.628 ccw(c69.587,73.161) U4.5@70.671,72.077 ; U4.5@70.851,71.359 ccw(c70.2,70.708) 70.2,71.628 ccw(c70.2,72.548) U4.5@70.851,71.897
K6: R2.7 U3.12 U4.6 减/温度.2 | length 81.1
  Top Layer w0.254: U3.12@62.484,76.073 cw(c62.484,74.54) 63.568,75.624 cw(c64.652,76.708) U3.12@63.119,76.708 ; U3.12@62.484,76.327 cw(c62.484,75.407) 63.134,76.058 cw(c63.785,76.708) U3.12@62.865,76.708 ; U3.12@62.484,76.708 63.627,75.565 63.627,72.517 R2.7@67.056,69.088 ; R2.7@66.421,69.088 ccw(c64.888,69.088) 65.972,70.172 ccw(c67.056,71.256) R2.7@67.056,69.723 ; R2.7@66.675,69.088 ccw(c65.755,69.088) 66.406,69.738 ccw(c67.056,70.389) R2.7@67.056,69.469
  Bottom Layer w0.254: 减/温度.2@35.56,88.9 减/温度.2@43.18,88.9 50.8,88.9 52.324,87.376 52.324,79.248 53.594,77.978 56.54,77.978 57.81,76.708 U3.12@62.484,76.708 ; 减/温度.2@35.829,88.631 cw(c36.48,87.98) 36.48,88.9 cw(c36.48,89.82) 减/温度.2@35.829,89.169 ; 减/温度.2@36.009,88.451 cw(c37.093,87.367) 37.093,88.9 cw(c37.093,90.433) 减/温度.2@36.009,89.349 ; 减/温度.2@42.731,88.451 ccw(c41.647,87.367) 41.647,88.9 ccw(c41.647,90.433) 减/温度.2@42.731,89.349 ; 减/温度.2@42.911,88.631 ccw(c42.26,87.98) 42.26,88.9 ccw(c42.26,89.82) 减/温度.2@42.911,89.169 ; 减/温度.2@43.449,88.631 cw(c44.1,87.98) 44.1,88.9 cw(c44.1,89.82) 减/温度.2@43.449,89.169 ; 减/温度.2@43.629,88.451 cw(c44.713,87.367) 44.713,88.9 cw(c44.713,90.433) 减/温度.2@43.629,89.349 ; U3.12@62.035,76.259 ccw(c60.951,75.175) 60.951,76.708 ccw(c60.951,78.241) U3.12@62.035,77.157 ; U3.12@62.215,76.439 ccw(c61.564,75.788) 61.564,76.708 ccw(c61.564,77.628) U3.12@62.215,76.977 ; R2.7@67.056,69.088 U4.6@71.12,69.088 ; R2.7@67.325,68.819 cw(c67.976,68.168) 67.976,69.088 cw(c67.976,70.008) R2.7@67.325,69.357 ; R2.7@67.505,68.639 cw(c68.589,67.555) 68.589,69.088 cw(c68.589,70.621) R2.7@67.505,69.537 ; U4.6@70.671,68.639 ccw(c69.587,67.555) 69.587,69.088 ccw(c69.587,70.621) U4.6@70.671,69.537 ; U4.6@70.851,68.819 ccw(c70.2,68.168) 70.2,69.088 ccw(c70.2,70.008) U4.6@70.851,69.357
